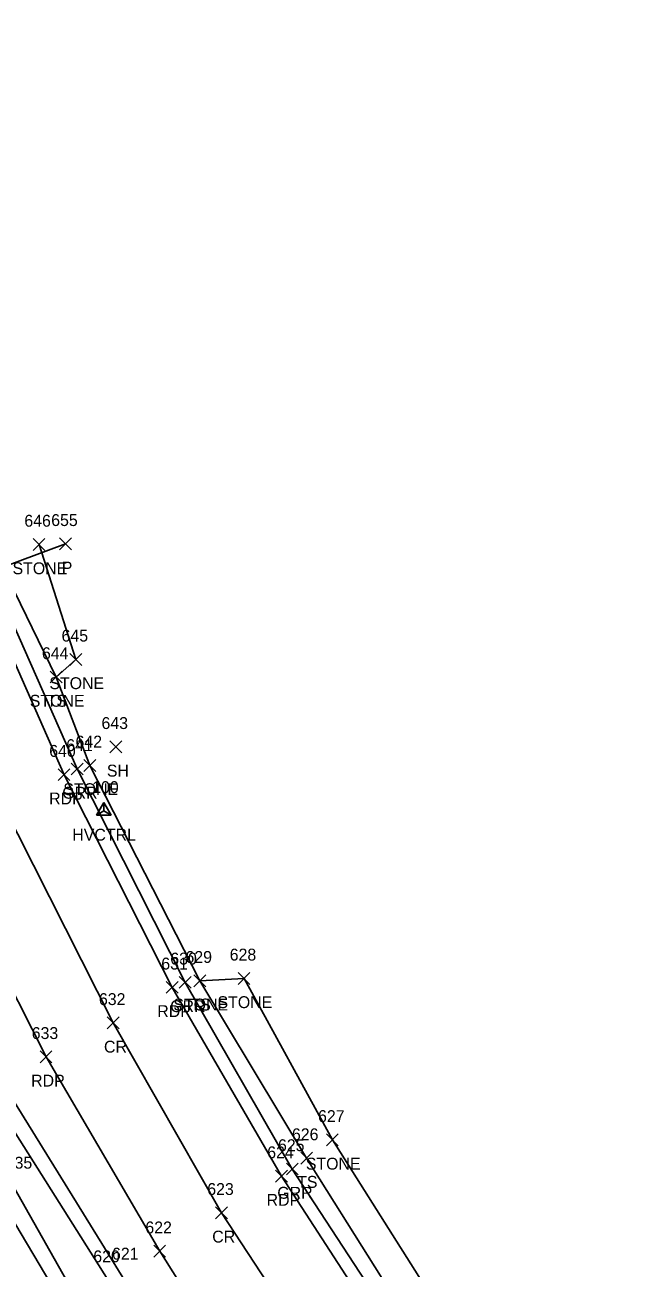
# Model space of a CAD drawing. Extents: x 1879695 to 1880991, y 836466 to 845172.
# Drawn here: x 1879887.6 to 1879991.4, y 844375.9 to 844585 of the extents above; entities that cross this region are included whole.
import ezdxf

# ---------------------------------------------------------------- set-up
doc = ezdxf.new("R2010")
doc.units = 0
for name, color, linetype in [('C_A', 7, 'Continuous'), ('C_I', 7, 'Continuous'), ('CPSM', 7, 'Continuous'), ('D_A', 7, 'Continuous'), ('D_I', 7, 'Continuous'), ('D_TIC', 7, 'Continuous'), ('DCP', 7, 'Continuous'), ('L_A', 7, 'Continuous'), ('L_I', 7, 'Continuous'), ('L_TIC', 7, 'Continuous'), ('LASF', 7, 'Continuous'), ('LAWA', 7, 'Continuous'), ('LELB', 7, 'Continuous'), ('P_A', 7, 'Continuous'), ('P_I', 7, 'Continuous'), ('P_TIC', 7, 'Continuous'), ('PET', 7, 'Continuous'), ('PRC', 7, 'Continuous'), ('R_A', 7, 'Continuous'), ('R_I', 7, 'Continuous'), ('R_TIC', 7, 'Continuous'), ('RGR', 7, 'Continuous')]:
    doc.layers.add(name, color=color, linetype=linetype)

msp = doc.modelspace()

# ---------------------------------------------------------------- linework, layer by layer
at = {"layer": 'CPSM'}
for p, q in [((1879899.61, 844452.07), (1879900.86, 844454.24)), ((1879902.11, 844452.07), (1879900.86, 844454.24)), ((1879900.86, 844452.8), (1879900.86, 844454.24)), ((1879899.61, 844452.07), (1879900.86, 844452.8)), ((1879899.61, 844452.07), (1879902.11, 844452.07)), ((1879900.86, 844452.8), (1879900.86, 844452.8)), ((1879900.86, 844452.8), (1879902.11, 844452.07))]:
    msp.add_line(p, q, dxfattribs=at)
at = {"layer": 'D_TIC'}
for points in [[(1879893.42, 844496.73), (1879895.42, 844498.73)], [(1879895.42, 844496.73), (1879893.42, 844498.73)]]:
    msp.add_lwpolyline(points, dxfattribs=at)
at = {"layer": 'DCP'}
msp.add_lwpolyline([(1879845.41, 844479.5), (1879894.42, 844497.73)], dxfattribs=at)
at = {"layer": 'L_TIC'}
for points in [[(1879888.96, 844496.62), (1879890.96, 844498.62)], [(1879890.96, 844496.62), (1879888.96, 844498.62)], [(1879895.16, 844477.29), (1879897.16, 844479.29)], [(1879897.16, 844477.29), (1879895.16, 844479.29)], [(1879891.86, 844474.33), (1879893.86, 844476.33)], [(1879893.86, 844474.33), (1879891.86, 844476.33)], [(1879891.86, 844474.33), (1879893.86, 844476.33)], [(1879893.86, 844474.33), (1879891.86, 844476.33)], [(1879901.88, 844462.58), (1879903.88, 844464.58)], [(1879903.88, 844462.58), (1879901.88, 844464.58)], [(1879897.51, 844459.46), (1879899.51, 844461.46)], [(1879899.51, 844459.46), (1879897.51, 844461.46)], [(1879916.02, 844423.23), (1879918.02, 844425.23)], [(1879918.02, 844423.23), (1879916.02, 844425.23)], [(1879916.02, 844423.23), (1879918.02, 844425.23)], [(1879918.02, 844423.23), (1879916.02, 844425.23)], [(1879923.45, 844423.63), (1879925.45, 844425.63)], [(1879925.45, 844423.63), (1879923.45, 844425.63)], [(1879938.31, 844396.46), (1879940.31, 844398.46)], [(1879940.31, 844396.46), (1879938.31, 844398.46)], [(1879933.98, 844393.4), (1879935.98, 844395.4)], [(1879935.98, 844393.4), (1879933.98, 844395.4)]]:
    msp.add_lwpolyline(points, dxfattribs=at)
at = {"layer": 'LASF'}
msp.add_lwpolyline([(1880139.87, 844182.06), (1880107.81, 844210.08), (1880073.67, 844241.21), (1880039.73, 844270.44), (1880011.8, 844299.45), (1879985.05, 844328.99), (1879962.59, 844360.65), (1879939.31, 844397.46), (1879924.45, 844424.63), (1879917.02, 844424.23), (1879898.51, 844460.46), (1879892.86, 844475.33), (1879896.16, 844478.29), (1879889.96, 844497.62)], dxfattribs=at)
at = {"layer": 'LAWA'}
msp.add_lwpolyline([(1879894.06, 844369.68), (1879882.81, 844388.57), (1879874.93, 844402.15), (1879867.06, 844417.11), (1879859.8, 844413.1), (1879850.22, 844404.26), (1879837.13, 844392.39), (1879819.57, 844382.71), (1879804.42, 844368.86)], dxfattribs=at)
at = {"layer": 'LELB'}
for points in [[(1879892.86, 844475.33), (1879883.81, 844493.88), (1879869.59, 844531.53), (1879857.27, 844570.41), (1879848, 844610.42), (1879840.98, 844651.69), (1879836.74, 844689.33), (1879832.5, 844735.02), (1879831.42, 844779.25), (1879830.94, 844828.14), (1879831.12, 844883.89), (1879831.78, 844926.93), (1879832.17, 844972.31), (1879832.24, 845014.04), (1879832.59, 845051.89), (1879833.37, 845086.82), (1879834.06, 845125.48), (1879835.58, 845163.13)], [(1880237.65, 844030.17), (1880225.55, 844045.25), (1880203.19, 844067.94), (1880175.04, 844095.38), (1880141.55, 844124.24), (1880111.59, 844152.12), (1880079.67, 844179.09), (1880044.89, 844208.16), (1880013.5, 844237.54), (1880003.34, 844247.82), (1879979.16, 844270.62), (1879948.51, 844300.87), (1879928.97, 844335.67), (1879901.59, 844373.87), (1879881.39, 844405.75), (1879863.37, 844445.07), (1879846.41, 844479.41), (1879833.35, 844517.23), (1879821, 844560.9), (1879811.24, 844600.26), (1879800.64, 844646.71), (1879794.2, 844680.16), (1879792.03, 844683.6), (1879789.08, 844683.63)], [(1880243.53, 844023.94), (1880226.64, 844046.28), (1880204.68, 844069.12), (1880177.19, 844097.39), (1880144.15, 844127.37), (1880114.34, 844154.46), (1880082.65, 844181.38), (1880047.53, 844211.78), (1880015.32, 844240.12), (1879982.29, 844271.84), (1879951.96, 844303.04), (1879930.28, 844336.91), (1879904.08, 844374.32), (1879883.92, 844406.9), (1879866.98, 844446.02), (1879852.23, 844482.49), (1879838.68, 844519.35), (1879826.86, 844562.48), (1879815.22, 844600.52)], [(1880274.18, 844042.18), (1880252.69, 844068.34), (1880228.42, 844092.99), (1880199.77, 844120.37), (1880165.71, 844151.73), (1880135.43, 844177.69), (1880104.5, 844206.3), (1880070.17, 844236.88), (1880037.83, 844267.79), (1880007.31, 844296.06), (1879981.71, 844326.11), (1879957.94, 844357.83), (1879934.98, 844394.4), (1879917.02, 844424.23)], [(1880002.51, 844242.73), (1879985.64, 844257.52), (1879965.17, 844278.62), (1879940.72, 844305.37), (1879925.82, 844326.46), (1879896.67, 844370.14), (1879885.64, 844389.62), (1879876.9, 844403.13), (1879868.08, 844418.79), (1879858.9, 844415.1), (1879849.52, 844405.96), (1879835.24, 844394.65), (1879817.98, 844385.29), (1879800.66, 844373.71), (1879774.59, 844370.4), (1879756.19, 844355.96), (1879741.66, 844350.26)]]:
    msp.add_lwpolyline(points, dxfattribs=at)
at = {"layer": 'P_TIC'}
for points in [[(1879893.17, 844457.9), (1879895.17, 844459.9)], [(1879895.17, 844457.9), (1879893.17, 844459.9)], [(1879911.37, 844422.12), (1879913.37, 844424.12)], [(1879913.37, 844422.12), (1879911.37, 844424.12)], [(1879901.45, 844416.14), (1879903.45, 844418.14)], [(1879903.45, 844416.14), (1879901.45, 844418.14)], [(1879890.14, 844410.43), (1879892.14, 844412.43)], [(1879892.14, 844410.43), (1879890.14, 844412.43)], [(1879929.76, 844390.37), (1879931.76, 844392.37)], [(1879931.76, 844390.37), (1879929.76, 844392.37)], [(1879919.67, 844384.19), (1879921.67, 844386.19)], [(1879921.67, 844384.19), (1879919.67, 844386.19)], [(1879909.26, 844377.73), (1879911.26, 844379.73)], [(1879911.26, 844377.73), (1879909.26, 844379.73)]]:
    msp.add_lwpolyline(points, dxfattribs=at)
at = {"layer": 'PET'}
for points in [[(1880269.75, 844039.67), (1880250.27, 844065.9), (1880225.97, 844090.31), (1880195.98, 844117.55), (1880162.1, 844148.13), (1880132.62, 844174.7), (1880101.36, 844203.03), (1880066.94, 844232.59), (1880034.5, 844263.16), (1880004.09, 844293.64), (1879978.17, 844323.39), (1879954.46, 844354.82), (1879930.76, 844391.37), (1879912.37, 844423.12), (1879894.17, 844458.9), (1879879.41, 844492.34), (1879865.46, 844529.81), (1879852.88, 844569.32), (1879843.17, 844608.03)], [(1880246.17, 844024.86), (1880229.35, 844048.54), (1880207.67, 844072.23), (1880179.65, 844099.99), (1880146.48, 844130.19), (1880116.3, 844156.76), (1880085.61, 844184.86), (1880050.42, 844215.32), (1880017.65, 844245.83), (1879986.99, 844277.13), (1879959.04, 844308.59), (1879934.2, 844340.79), (1879910.26, 844378.73), (1879891.14, 844411.43), (1879872.36, 844448.44), (1879856.33, 844484.43), (1879842.37, 844521.56), (1879829.6, 844563.28), (1879820.43, 844602.23)]]:
    msp.add_lwpolyline(points, dxfattribs=at)
at = {"layer": 'PRC'}
msp.add_lwpolyline([(1880256.85, 844032.04), (1880238.91, 844056.2), (1880216.7, 844080.65), (1880187.27, 844108.93), (1880154.23, 844138.82), (1880124.19, 844165.48), (1880092.74, 844193.41), (1880058.56, 844223.39), (1880025.99, 844253.92), (1879995.14, 844285.41), (1879968.79, 844316.24), (1879945.09, 844347.91), (1879920.67, 844385.19), (1879902.45, 844417.14), (1879883.72, 844454.21), (1879868.53, 844488.38), (1879854.47, 844526.01), (1879841.81, 844566.38), (1879832.13, 844605)], dxfattribs=at)
at = {"layer": 'R_TIC'}
for points in [[(1879895.38, 844458.86), (1879897.38, 844460.86)], [(1879897.38, 844458.86), (1879895.38, 844460.86)], [(1879913.54, 844422.96), (1879915.54, 844424.96)], [(1879915.54, 844422.96), (1879913.54, 844424.96)], [(1879931.57, 844391.56), (1879933.57, 844393.56)], [(1879933.57, 844391.56), (1879931.57, 844393.56)]]:
    msp.add_lwpolyline(points, dxfattribs=at)
at = {"layer": 'RGR'}
msp.add_lwpolyline([(1880270.9, 844040.93), (1880251.09, 844066.69), (1880226.93, 844091.38), (1880197.34, 844118.12), (1880162.87, 844149.15), (1880133.45, 844175.62), (1880101.92, 844203.72), (1880067.67, 844234.21), (1880035.3, 844264.37), (1880005.3, 844294.8), (1879979.45, 844324.37), (1879956.29, 844356.24), (1879932.57, 844392.56), (1879914.54, 844423.96), (1879896.38, 844459.86), (1879881.66, 844493.03), (1879867.6, 844530.61), (1879855.21, 844570.01), (1879845.36, 844608.98)], dxfattribs=at)

# ---------------------------------------------------------------- texts
at = {"layer": 'C_A'}
msp.add_text('HVCTRL', height=2, dxfattribs=at).set_placement((1879895.56, 844447.8))
at = {"layer": 'C_I'}
msp.add_text('100', height=2, dxfattribs=at).set_placement((1879898.9, 844455.8))
at = {"layer": 'D_A'}
msp.add_text('P', height=2, dxfattribs=at).set_placement((1879893.79, 844492.73))
at = {"layer": 'D_I'}
msp.add_text('655', height=2, dxfattribs=at).set_placement((1879892.01, 844500.73))
at = {"layer": 'L_A'}
for s, p in [('STONE', (1879885.5, 844492.62)), ('STONE', (1879891.7, 844473.29)), ('STONE', (1879888.4, 844470.33)), ('TS', (1879891.27, 844470.33)), ('SH', (1879901.37, 844458.58)), ('STONE', (1879894.05, 844455.46)), ('STONE', (1879912.56, 844419.23)), ('TS', (1879915.43, 844419.23)), ('STONE', (1879919.99, 844419.63)), ('STONE', (1879934.85, 844392.46)), ('TS', (1879933.39, 844389.4))]:
    msp.add_text(s, height=2, dxfattribs=at).set_placement(p)
at = {"layer": 'L_I'}
for s, p in [('646', (1879887.49, 844500.62)), ('645', (1879893.75, 844481.29)), ('644', (1879890.45, 844478.33)), ('644', (1879890.45, 844478.33)), ('643', (1879900.47, 844466.58)), ('642', (1879896.1, 844463.46)), ('629', (1879914.6, 844427.23)), ('629', (1879914.6, 844427.23)), ('628', (1879922.04, 844427.63)), ('627', (1879936.9, 844400.46)), ('626', (1879932.51, 844397.4)), ('1035', (1879882.87, 844392.62)), ('620', (1879899.09, 844376.87)), ('621', (1879902.24, 844377.32))]:
    msp.add_text(s, height=2, dxfattribs=at).set_placement(p)
at = {"layer": 'P_A'}
for s, p in [('RDP', (1879891.66, 844453.9)), ('RDP', (1879909.86, 844418.12)), ('CR', (1879900.89, 844412.14)), ('RDP', (1879888.63, 844406.43)), ('RDP', (1879928.25, 844386.37)), ('CR', (1879919.1, 844380.19))]:
    msp.add_text(s, height=2, dxfattribs=at).set_placement(p)
at = {"layer": 'P_I'}
for s, p in [('640', (1879891.68, 844461.9)), ('631', (1879910.53, 844426.12)), ('632', (1879900.04, 844420.14)), ('633', (1879888.73, 844414.43)), ('624', (1879928.35, 844394.37)), ('623', (1879918.26, 844388.19)), ('622', (1879907.85, 844381.73))]:
    msp.add_text(s, height=2, dxfattribs=at).set_placement(p)
at = {"layer": 'R_A'}
for p in [(1879893.87, 844454.86), (1879912.03, 844418.96), (1879930.05, 844387.56)]:
    msp.add_text('GRR', height=2, dxfattribs=at).set_placement(p)
at = {"layer": 'R_I'}
for s, p in [('641', (1879894.54, 844462.86)), ('630', (1879912.05, 844426.96)), ('625', (1879930.16, 844395.56))]:
    msp.add_text(s, height=2, dxfattribs=at).set_placement(p)

doc.saveas('drawing.dxf')
